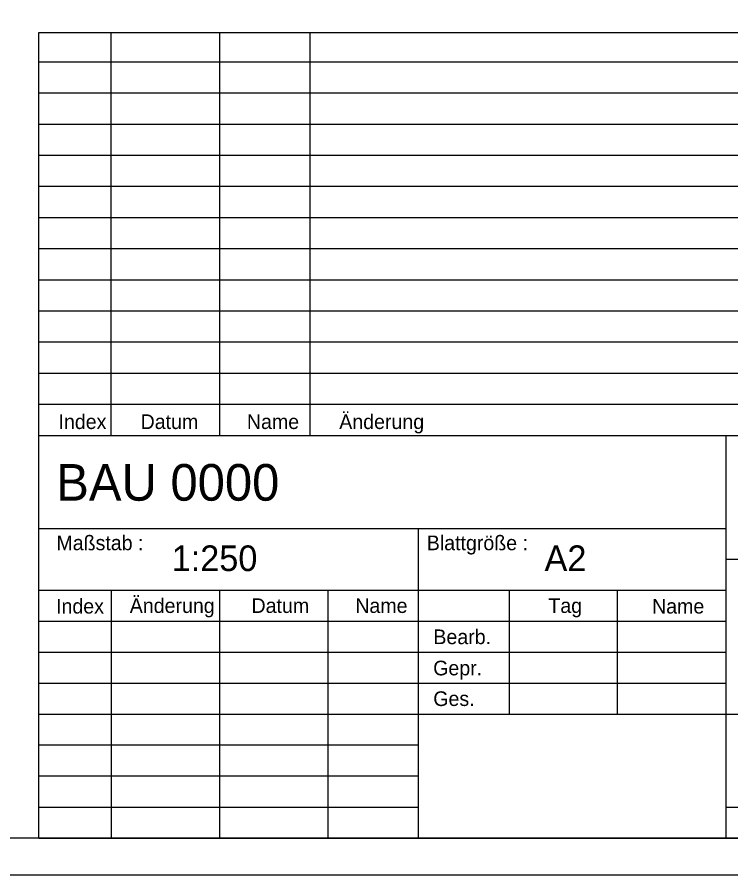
# Model space of a CAD drawing. Extents: x 0 to 148, y 0 to 105.
# Drawn here: x 102.04 to 126.41, y 0 to 29.27 of the extents above; entities that cross this region are included whole.
import ezdxf

# ---------------------------------------------------------------- set-up
doc = ezdxf.new("R2010")
doc.units = 0
doc.layers.add('90_Plankopf', color=7, linetype='Continuous')

msp = doc.modelspace()

# ---------------------------------------------------------------- linework, layer by layer
at = {"layer": '90_Plankopf'}
for p, q in [((102.78, 14.998), (102.78, 28.745)), ((102.78, 28.745), (147.25, 28.745)), ((105.251, 14.998), (105.251, 28.745)), ((108.957, 14.998), (108.957, 28.745)), ((112.045, 14.998), (112.045, 28.745)), ((102.78, 27.748), (147.25, 27.748)), ((102.78, 26.685), (147.25, 26.685)), ((102.78, 25.623), (147.25, 25.623)), ((102.78, 24.56), (147.25, 24.56)), ((102.78, 23.498), (147.25, 23.498)), ((102.78, 22.435), (147.25, 22.435)), ((102.78, 21.373), (147.25, 21.373)), ((102.78, 20.31), (147.25, 20.31)), ((102.78, 19.248), (147.25, 19.248)), ((102.78, 18.185), (147.25, 18.185)), ((102.78, 17.123), (147.25, 17.123)), ((102.78, 16.06), (147.25, 16.06)), ((102.78, 14.998), (147.25, 14.998)), ((102.78, 1.25), (102.78, 14.998)), ((102.78, 14.998), (147.25, 14.998)), ((126.25, 1.25), (126.25, 14.998)), ((102.78, 11.825), (126.25, 11.825)), ((115.751, 1.25), (115.751, 11.825)), ((126.25, 10.768), (147.25, 10.768)), ((102.78, 9.718), (126.25, 9.718)), ((105.251, 9.71), (105.251, 1.25)), ((108.957, 1.25), (108.957, 9.71)), ((112.662, 1.25), (112.662, 9.71)), ((118.839, 9.71), (118.839, 5.48)), ((122.544, 5.48), (122.544, 9.71)), ((102.78, 8.658), (126.25, 8.658)), ((102.78, 7.595), (126.25, 7.595)), ((102.78, 6.538), (126.25, 6.538)), ((102.78, 5.48), (126.25, 5.48)), ((102.78, 5.48), (126.25, 5.48)), ((115.751, 5.48), (126.25, 5.48)), ((126.25, 5.48), (147.25, 5.48)), ((115.751, 4.423), (102.78, 4.423)), ((115.751, 3.365), (102.78, 3.365)), ((102.78, 2.308), (115.751, 2.308)), ((126.25, 2.308), (147.25, 2.308)), ((147.25, 1.25), (102.78, 1.25)), ((102.78, 1.25), (115.751, 1.25)), ((105.7, 1.25), (147.25, 1.25)), ((105.7, 1.25), (147.25, 1.25))]:
    msp.add_line(p, q, dxfattribs=at)
for points in [[(0, 0), (148.5, 0), (148.5, 105), (0, 105)], [(6.25, 103.75), (147.25, 103.75), (147.25, 1.25), (6.25, 1.25)]]:
    msp.add_lwpolyline(points, close=True, dxfattribs=at)

# ---------------------------------------------------------------- texts
for s, height, p in [('Änderung', 0.5, (113.039, 15.214)), ('Index', 0.5, (103.451, 15.214)), ('Datum', 0.5, (106.254, 15.214)), ('Name', 0.5, (109.885, 15.214)), ('BAU 0000      ', 1.25, (103.373, 12.769)), ('Maßstab :', 0.5, (103.379, 11.079)), ('Blattgröße :', 0.49998, (116.029, 11.079)), ('1:250    ', 0.875, (107.315, 10.367)), ('A2       ', 0.875, (120.05, 10.367)), ('Index', 0.5, (103.367, 8.918)), ('Änderung', 0.5, (105.884, 8.937)), ('Datum', 0.5, (110.042, 8.937)), ('Name', 0.5, (113.587, 8.937)), ('Tag', 0.5, (120.181, 8.937)), ('Name', 0.5, (123.723, 8.918)), ('Bearb.', 0.5, (116.254, 7.873)), ('Gepr.', 0.5, (116.247, 6.808)), ('Ges.', 0.5, (116.251, 5.762))]:
    msp.add_text(s, height=height, dxfattribs=at).set_placement(p)

doc.saveas('drawing.dxf')
